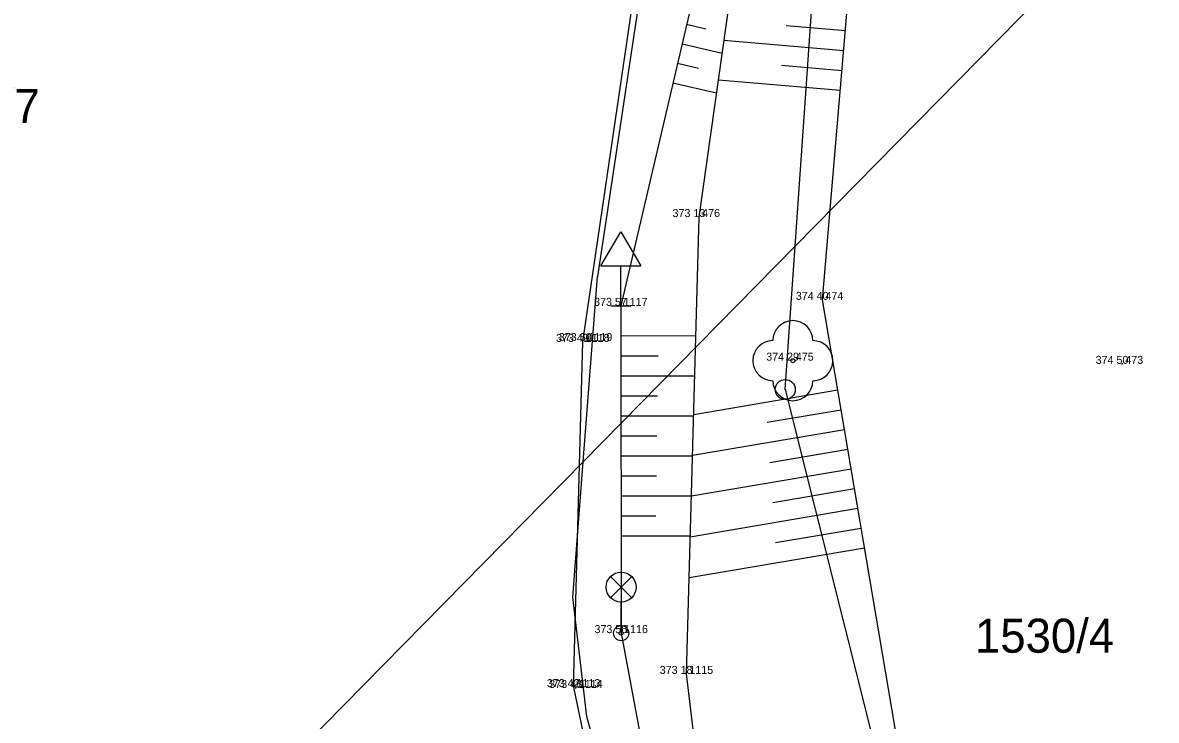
# Model space of a CAD drawing. Extents: x -601196 to -600262, y -1082523 to -1081922.
# Drawn here: x -600520.42 to -600492.1, y -1082177.56 to -1082160.12 of the extents above; entities that cross this region are included whole.
import ezdxf

# ---------------------------------------------------------------- set-up
doc = ezdxf.new("R2010")
doc.units = 0
for name, color, linetype in [('Vrstva 1', 7, 'Continuous'), ('Vrstva 10', 7, 'Continuous'), ('Vrstva 14', 7, 'Continuous'), ('Vrstva 2', 7, 'Continuous'), ('Vrstva 20', 7, 'Continuous'), ('Vrstva 22', 7, 'Continuous'), ('Vrstva 25', 7, 'Continuous'), ('Vrstva 3', 7, 'Continuous'), ('Vrstva 33', 7, 'Continuous'), ('Vrstva 34', 7, 'Continuous'), ('Vrstva 47', 7, 'Continuous')]:
    doc.layers.add(name, color=color, linetype=linetype)

msp = doc.modelspace()

# ---------------------------------------------------------------- linework, layer by layer
at = {"layer": 'Vrstva 1'}
for p, q in [((-600503.52, -1082164.98), (-600503.52, -1082164.98)), ((-600505.48, -1082167.2), (-600505.48, -1082167.2)), ((-600500.44, -1082167.05), (-600500.44, -1082167.05)), ((-600506.43, -1082168.1), (-600506.43, -1082168.1)), ((-600506.36, -1082168.08), (-600506.36, -1082168.08)), ((-600501.18, -1082168.57), (-600501.18, -1082168.57)), ((-600492.95, -1082168.65), (-600492.95, -1082168.65)), ((-600505.47, -1082175.38), (-600505.47, -1082175.38)), ((-600503.84, -1082176.4), (-600503.84, -1082176.4)), ((-600506.66, -1082176.73), (-600506.66, -1082176.73)), ((-600506.6, -1082176.75), (-600506.6, -1082176.75))]:
    msp.add_line(p, q, dxfattribs=at)
at = {"layer": 'Vrstva 10'}
for p, q in [((-600506.43, -1082168.1), (-600505.01, -1082158.47)), ((-600506.66, -1082176.73), (-600506.43, -1082168.1))]:
    msp.add_line(p, q, dxfattribs=at)
msp.add_lwpolyline([(-600506.66, -1082176.73), (-600506.53, -1082177.372), (-600506.392, -1082178.012), (-600506.246, -1082178.651), (-600506.092, -1082179.287), (-600505.931, -1082179.922), (-600505.762, -1082180.555), (-600505.585, -1082181.185), (-600505.4, -1082181.814), (-600505.208, -1082182.44), (-600505.008, -1082183.063), (-600504.801, -1082183.685), (-600504.586, -1082184.303), (-600504.363, -1082184.919), (-600504.133, -1082185.532), (-600503.895, -1082186.143), (-600503.65, -1082186.75), (-600503.398, -1082187.354), (-600503.138, -1082187.956), (-600503.11, -1082188.02)], dxfattribs=at)
at = {"layer": 'Vrstva 14'}
for p, q in [((-600503.52, -1082164.98), (-600502.46, -1082157.43)), ((-600500.44, -1082167.05), (-600499.67, -1082158.01)), ((-600503.84, -1082176.4), (-600503.52, -1082164.98)), ((-600497.79, -1082182.67), (-600500.44, -1082167.05)), ((-600505.47, -1082175.38), (-600503.11, -1082188.02)), ((-600503.07, -1082182.72), (-600503.84, -1082176.4))]:
    msp.add_line(p, q, dxfattribs=at)
msp.add_lwpolyline([(-600503.07, -1082156.9), (-600505.48, -1082167.2), (-600505.47, -1082175.38)], dxfattribs=at)
at = {"layer": 'Vrstva 20'}
for p, q in [((-600506.37, -1082168.08), (-600506.35, -1082168.08)), ((-600506.36, -1082168.065), (-600506.36, -1082168.08)), ((-600506.36, -1082168.095), (-600506.36, -1082168.08)), ((-600492.96, -1082168.65), (-600492.94, -1082168.65)), ((-600492.95, -1082168.635), (-600492.95, -1082168.65)), ((-600492.95, -1082168.665), (-600492.95, -1082168.65)), ((-600506.61, -1082176.75), (-600506.59, -1082176.75)), ((-600506.6, -1082176.735), (-600506.6, -1082176.75)), ((-600506.6, -1082176.765), (-600506.6, -1082176.75))]:
    msp.add_line(p, q, dxfattribs=at)
at = {"layer": 'Vrstva 22'}
msp.add_circle((-600501.18, -1082168.57), 0.05, dxfattribs=at)
for centre, start, end in [((-600501.18, -1082168.07), 0, 180), ((-600501.68, -1082168.57), 90, 270), ((-600500.68, -1082168.57), 270, 90), ((-600501.18, -1082169.07), 180, 0)]:
    msp.add_arc(centre, 0.5, start, end, dxfattribs=at)
at = {"layer": 'Vrstva 25'}
for p, q in [((-600503.833, -1082160.163), (-600503.354, -1082160.275)), ((-600499.867, -1082160.325), (-600501.349, -1082160.199)), ((-600503.947, -1082160.65), (-600502.945, -1082160.884)), ((-600499.91, -1082160.823), (-600502.901, -1082160.569)), ((-600504.061, -1082161.137), (-600503.538, -1082161.259)), ((-600499.952, -1082161.322), (-600501.461, -1082161.193)), ((-600504.175, -1082161.623), (-600503.085, -1082161.878)), ((-600499.995, -1082161.82), (-600503.04, -1082161.56)), ((-600505.479, -1082167.947), (-600503.603, -1082167.945)), ((-600505.478, -1082168.447), (-600504.548, -1082168.446)), ((-600505.478, -1082168.947), (-600503.631, -1082168.945)), ((-600505.477, -1082169.447), (-600504.561, -1082169.446)), ((-600500.056, -1082169.311), (-600503.658, -1082169.922)), ((-600499.973, -1082169.804), (-600501.823, -1082170.117)), ((-600505.477, -1082169.947), (-600503.659, -1082169.945)), ((-600499.889, -1082170.296), (-600503.687, -1082170.941)), ((-600505.476, -1082170.447), (-600504.575, -1082170.446)), ((-600505.475, -1082170.947), (-600503.687, -1082170.945)), ((-600499.806, -1082170.789), (-600501.753, -1082171.12)), ((-600505.475, -1082171.447), (-600504.588, -1082171.446)), ((-600499.722, -1082171.282), (-600503.716, -1082171.96)), ((-600499.638, -1082171.775), (-600501.684, -1082172.122)), ((-600505.474, -1082171.947), (-600503.715, -1082171.945)), ((-600499.555, -1082172.268), (-600503.744, -1082172.979)), ((-600505.474, -1082172.447), (-600504.601, -1082172.446)), ((-600505.473, -1082172.947), (-600503.743, -1082172.945)), ((-600499.471, -1082172.761), (-600501.615, -1082173.125)), ((-600499.387, -1082173.254), (-600503.773, -1082173.998))]:
    msp.add_line(p, q, dxfattribs=at)
at = {"layer": 'Vrstva 33'}
for p, q in [((-600505.735, -1082173.965), (-600505.205, -1082174.495)), ((-600505.735, -1082174.495), (-600505.205, -1082173.965)), ((-600505.47, -1082175.38), (-600505.47, -1082174.605))]:
    msp.add_line(p, q, dxfattribs=at)
for centre, radius in [((-600505.47, -1082174.23), 0.375), ((-600505.47, -1082175.38), 0.19), ((-600505.47, -1082175.38), 0.05)]:
    msp.add_circle(centre, radius, dxfattribs=at)
at = {"layer": 'Vrstva 34'}
for p, q in [((-600505.98, -1082166.2), (-600505.48, -1082165.35)), ((-600505.48, -1082165.35), (-600504.98, -1082166.2)), ((-600505.98, -1082166.2), (-600504.98, -1082166.2)), ((-600505.48, -1082167.2), (-600505.48, -1082166.2)), ((-600505.73, -1082167.2), (-600505.23, -1082167.2))]:
    msp.add_line(p, q, dxfattribs=at)
at = {"layer": 'Vrstva 47'}
for p, q in [((-600501.12, -1082165.71), (-600499.16, -1082137.22)), ((-600504.27, -1082154.53), (-600506.06, -1082166.47)), ((-600501.12, -1082165.71), (-600492.1, -1082156.53)), ((-600501.12, -1082165.71), (-600506.42, -1082171.1)), ((-600501.37, -1082169.29), (-600501.12, -1082165.71)), ((-600506.42, -1082171.1), (-600506.06, -1082166.47)), ((-600501.37, -1082169.29), (-600494.74, -1082195.8)), ((-600515.25, -1082180.08), (-600506.42, -1082171.1)), ((-600506.68, -1082174.48), (-600506.42, -1082171.1)), ((-600506.33, -1082177.46), (-600506.68, -1082174.48)), ((-600504.75, -1082183.28), (-600506.33, -1082177.46))]:
    msp.add_line(p, q, dxfattribs=at)
for radius in [0.25, 0.005]:
    msp.add_circle((-600501.37, -1082169.29), radius, dxfattribs=at)

# ---------------------------------------------------------------- texts
at = {"layer": 'Vrstva 2'}
for s, p in [(' 476', (-600503.52, -1082164.98)), (' 1117', (-600505.48, -1082167.2)), (' 474', (-600500.44, -1082167.05)), (' 1118', (-600506.43, -1082168.1)), (' 1119', (-600506.36, -1082168.08)), (' 475', (-600501.18, -1082168.57)), (' 473', (-600492.95, -1082168.65)), (' 1116', (-600505.47, -1082175.38)), (' 1115', (-600503.84, -1082176.4)), (' 1113', (-600506.66, -1082176.73)), (' 1114', (-600506.6, -1082176.75))]:
    msp.add_text(s, height=0.2, dxfattribs=at).set_placement(p)
at = {"layer": 'Vrstva 3'}
for s, p in [('373 13 ', (-600504.186, -1082164.98)), ('373 57 ', (-600506.146, -1082167.2)), ('374 40 ', (-600501.106, -1082167.05)), ('373 49 ', (-600507.096, -1082168.1)), ('373 60 ', (-600507.026, -1082168.08)), ('374 29 ', (-600501.846, -1082168.57)), ('374 50 ', (-600493.616, -1082168.65)), ('373 56 ', (-600506.136, -1082175.38)), ('373 18 ', (-600504.506, -1082176.4)), ('373 42 ', (-600507.326, -1082176.73)), ('373 48 ', (-600507.266, -1082176.75))]:
    msp.add_text(s, height=0.2, dxfattribs=at).set_placement(p)
at = {"layer": 'Vrstva 47'}
for s, p in [('1525/7', (-600523.47, -1082162.63)), ('1530/4', (-600496.63, -1082175.87))]:
    msp.add_text(s, height=0.85, dxfattribs=at).set_placement(p)

doc.saveas('drawing.dxf')
